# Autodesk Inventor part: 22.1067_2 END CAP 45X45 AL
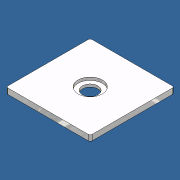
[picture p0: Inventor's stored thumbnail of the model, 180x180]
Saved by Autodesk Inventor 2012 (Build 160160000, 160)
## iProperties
Created: 2007-01
Part Number: 22.1067_2 END CAP 45X45 AL
Document SubType Name: Modeling
Designer: Andy Moles
Density: 2.71 g/cm^3
Material: Aluminum-6061
Mass: 15.6861 g
Surface Area: 45.7603 cm^2
Volume: 5.78824 cm^3
Description: 45x45 AL END CAP
Stock Number: 21.9522 AL SHEET 3/32"
Vendor: F
FINISH: ETCH & CLEAR ANODIZE
Author: Andy Moles
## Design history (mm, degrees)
sketch "Sketch1"
  geometry: L1 (-22.5, -22.5)-(22.5, -22.5); L2 (22.5, -22.5)-(22.5, 22.5); L3 (22.5, 22.5)-(-22.5, 22.5); L4 (-22.5, 22.5)-(-22.5, -22.5); L5 (-22.5, 22.5)-(22.5, -22.5); C1 r 4.1 at (0, 0); 2 further points
  constraints: 10 end point, 2 coincident, 2 parallel, 1 centre point, 1 horizontal, 1 midpoint, 1 perpendicular
  dimensions: "d0" = 45 distance of L2.end L3.end; "d1" = 45 distance of L3.end L1.start; "d2" = 8.2 diameter of C1
extrude "Extrusion1" new body sketch "Sketch1" distance "d3" = 3; taper "d4" = 0 deg
fillet "Fillet1" dims "d5" = 1
hole "Hole1" diameter "d8" = 8.3; stored, may be unused: countersink angle "d12" = 90 deg, drill point angle "d14" = 118 deg; dims "d6" = 10, "d7" = 10, "d9" = 6, "d10" = 13, "d11" = 1.55, "d13" = 8
body "Solid1"
